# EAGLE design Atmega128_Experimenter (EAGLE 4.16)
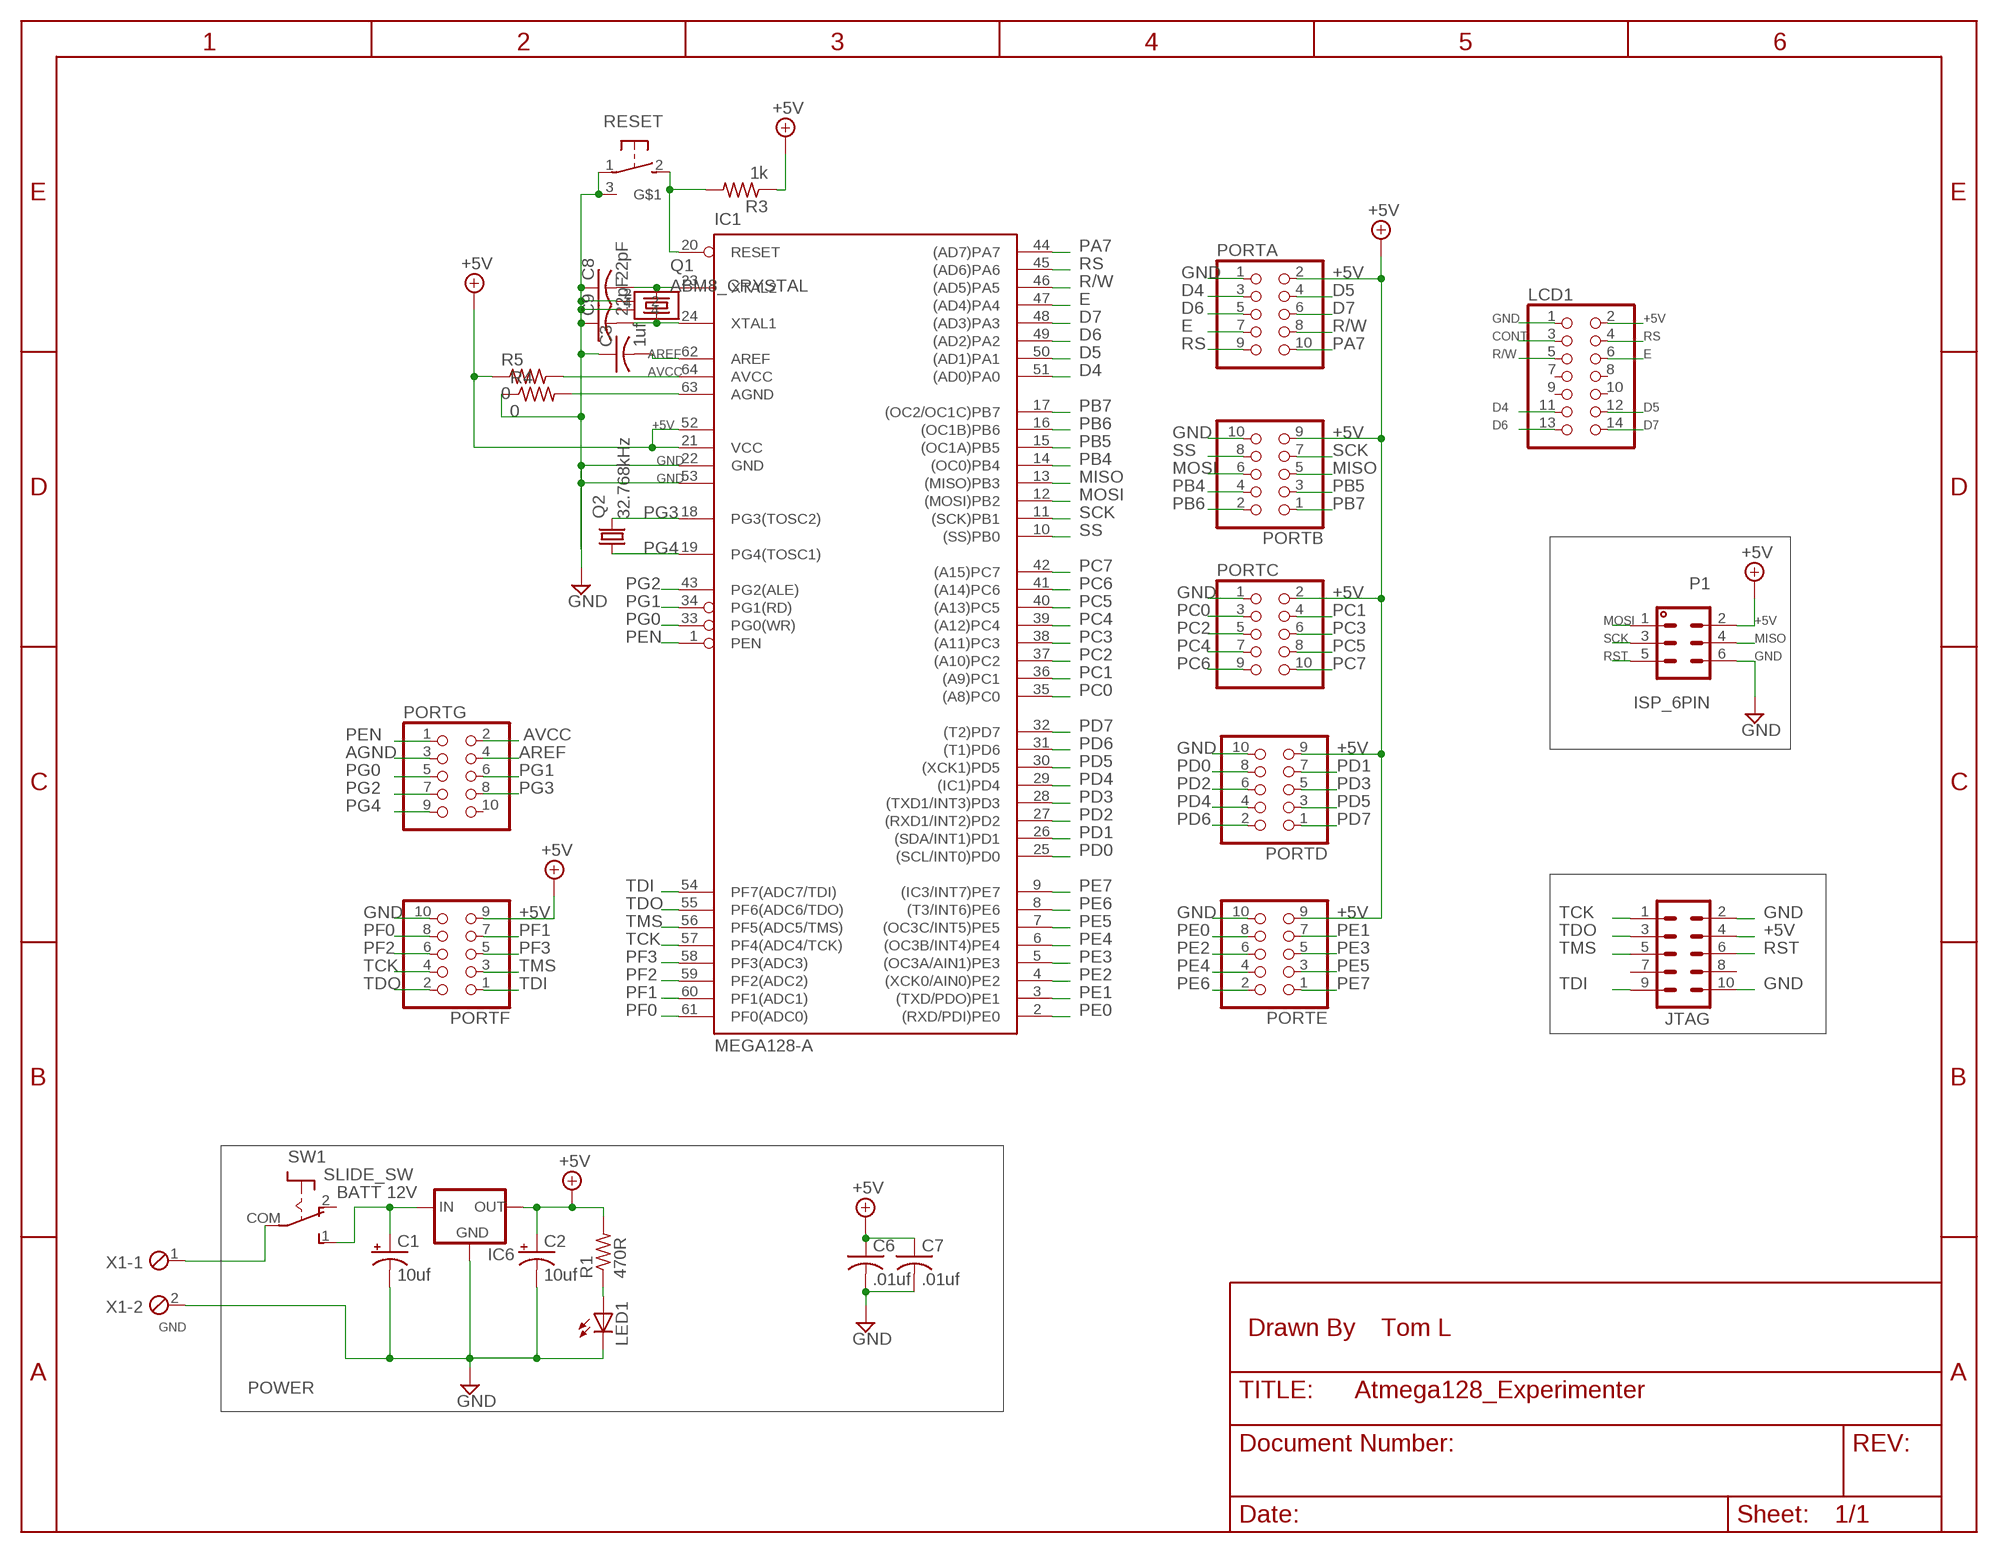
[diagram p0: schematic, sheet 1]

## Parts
C1  10uf  CPOL-US153CLV-0505  [153CLV-0505]
C2  10uf  CPOL-US153CLV-0505  [153CLV-0505]
C3  1uf  C-USC0603  [C0603]
C6  .01uf  C-USC0603  [C0603]
C7  .01uf  C-USC0603  [C0603]
C8  22pF  C-USC0603  [C0603]
C9  22pF  C-USC0603  [C0603]
IC1  MEGA128-A  [TQFP64]
IC6  78XXL  [78XXL]
JTAG  MA05-2  [MA05-2]
LCD1  PINHD-2X7  [2X07]
LED1  LEDCHIP-LED0805  [CHIP-LED0805]
P1  ISP_6PIN  [2X03]
PORTA  PINHD-2X5  [2X05]
PORTB  PINHD-2X5  [2X05]
PORTC  PINHD-2X5  [2X05]
PORTD  PINHD-2X5  [2X05]
PORTE  PINHD-2X5  [2X05]
PORTF  PINHD-2X5  [2X05]
PORTG  PINHD-2X5  [2X05]
Q1  ABM8_CRYSTAL  [ABM8]
Q2  32.768kHz  CRYTALTC26V  [TC26V]
R1  470R  R-US_R0603  [R0603]
R3  1k  R-US_R0603  [R0603]
R4  0  R-US_R0603  [R0603]
R5  0  R-US_R0603  [R0603]
RESET  B3U  [B3U]
SW1  SLIDE_SW  [EG1218]
X1  MPT2  [2POL254]

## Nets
12V_IN: SW1.COM X1.1
+5V: C2.+ C6.1 C7.1 IC1.21(VCC) IC1.52(VCC1) IC6.OUT JTAG.4 LCD1.2 P1.2(VDD) PORTA.2 PORTB.9 PORTC.2 PORTD.9 PORTE.9 PORTF.9 R1.2 R3.1 R5.1
+12V: C1.+ IC6.IN SW1.1
AGND: IC1.63(AGND) PORTG.3 R4.2
AREF: C3.2 IC1.62(AREF) PORTG.4
AVCC: IC1.64(AVCC) PORTG.2 R5.2
CONT: LCD1.3
D4: IC1.51((AD0)PA0) LCD1.11 PORTA.3
D5: IC1.50((AD1)PA1) LCD1.12 PORTA.4
D6: IC1.49((AD2)PA2) LCD1.13 PORTA.5
D7: IC1.48((AD3)PA3) LCD1.14 PORTA.6
E: IC1.47((AD4)PA4) LCD1.6 PORTA.7
GND: C1.- C2.- C3.1 C6.2 C7.2 C8.1 C9.1 IC1.22(GND) IC1.53(GND1) IC6.GND JTAG.2 JTAG.10 LCD1.1 LED1.C P1.6(GND) PORTA.1 PORTB.10 PORTC.1 PORTD.10 PORTE.10 PORTF.10 Q1.2 Q1.4 R4.1 RESET.1 RESET.3(G$1) X1.2
MISO: IC1.13((MISO)PB3) P1.4(MISO) PORTB.5
MOSI: IC1.12((MOSI)PB2) P1.1(MOSI) PORTB.6
N$5: LED1.A R1.1
PA7: IC1.44((AD7)PA7) PORTA.10
PB4: IC1.14((OC0)PB4) PORTB.4
PB5: IC1.15((OC1A)PB5) PORTB.3
PB6: IC1.16((OC1B)PB6) PORTB.2
PB7: IC1.17((OC2/OC1C)PB7) PORTB.1
PC0: IC1.35((A8)PC0) PORTC.3
PC1: IC1.36((A9)PC1) PORTC.4
PC2: IC1.37((A10)PC2) PORTC.5
PC3: IC1.38((A11)PC3) PORTC.6
PC4: IC1.39((A12)PC4) PORTC.7
PC5: IC1.40((A13)PC5) PORTC.8
PC6: IC1.41((A14)PC6) PORTC.9
PC7: IC1.42((A15)PC7) PORTC.10
PD0: IC1.25((SCL/INT0)PD0) PORTD.8
PD1: IC1.26((SDA/INT1)PD1) PORTD.7
PD2: IC1.27((RXD1/INT2)PD2) PORTD.6
PD3: IC1.28((TXD1/INT3)PD3) PORTD.5
PD4: IC1.29((IC1)PD4) PORTD.4
PD5: IC1.30((XCK1)PD5) PORTD.3
PD6: IC1.31((T1)PD6) PORTD.2
PD7: IC1.32((T2)PD7) PORTD.1
PE0: IC1.2((RXD/PDI)PE0) PORTE.8
PE1: IC1.3((TXD/PDO)PE1) PORTE.7
PE2: IC1.4((XCK0/AIN0)PE2) PORTE.6
PE3: IC1.5((OC3A/AIN1)PE3) PORTE.5
PE4: IC1.6((OC3B/INT4)PE4) PORTE.4
PE5: IC1.7((OC3C/INT5)PE5) PORTE.3
PE6: IC1.8((T3/INT6)PE6) PORTE.2
PE7: IC1.9((IC3/INT7)PE7) PORTE.1
PEN: IC1.1(PEN) PORTG.1
PF0: IC1.61(PF0(ADC0)) PORTF.8
PF1: IC1.60(PF1(ADC1)) PORTF.7
PF2: IC1.59(PF2(ADC2)) PORTF.6
PF3: IC1.58(PF3(ADC3)) PORTF.5
PG0: IC1.33(PG0(WR)) PORTG.5
PG1: IC1.34(PG1(RD)) PORTG.6
PG2: IC1.43(PG2(ALE)) PORTG.7
PG3: IC1.18(PG3(TOSC2)) PORTG.8 Q2.2
PG4: IC1.19(PG4(TOSC1)) PORTG.9 Q2.1
R/W: IC1.46((AD5)PA5) LCD1.5 PORTA.8
RS: IC1.45((AD6)PA6) LCD1.4 PORTA.9
RST: IC1.20(RESET) JTAG.6 P1.5(RST) R3.2 RESET.2
SCK: IC1.11((SCK)PB1) P1.3(SCK) PORTB.7
SS: IC1.10((SS)PB0) PORTB.8
TCK: IC1.57(PF4(ADC4/TCK)) JTAG.1 PORTF.4
TDI: IC1.54(PF7(ADC7/TDI)) JTAG.9 PORTF.1
TDO: IC1.55(PF6(ADC6/TDO)) JTAG.3 PORTF.2
TMS: IC1.56(PF5(ADC5/TMS)) JTAG.5 PORTF.3
XTAL1: C9.2 IC1.24(XTAL1) Q1.1
XTAL2: C8.2 IC1.23(XTAL2) Q1.3
Unconnected: JTAG.7 JTAG.8 LCD1.7 LCD1.8 LCD1.9 LCD1.10 PORTG.10 SW1.2

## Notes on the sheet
- BATT 12V
- Drawn By | Tom L
- POWER

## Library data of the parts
C1 C2 = rcl:CPOL-US: POLARIZED CAPACITOR, American symbol
C3 C6-C9 = rcl:C-US: CAPACITOR, American symbol
IC1 = atmel:MEGA128: MICROCONTROLLER 128 Kbytes FLASH 4 Kbytes SRAM 4 Kbytes EEPROM DUAL USART 8-channel 10 bit ADC Source: avr.lbr
IC6 = v-reg:78XXL: VOLTAGE REGULATOR
JTAG = con-lstb:MA05-2: PIN HEADER
LCD1 = pinhead:PINHD-2X7: PIN HEADER
LED1 = led:LED: LED
P1 = mylib:ISP_6PIN: AVR 6Pin ISP Connector
PORTA PORTB PORTC PORTD PORTE PORTF PORTG = pinhead:PINHD-2X5: PIN HEADER
Q1 = mylib:ABM8_CRYSTAL: Crystal SMD ABM8-16.000MHZ-B2-T
Q2 = crystal:CRYTAL: CRYSTAL
R1 R3-R5 = rcl:R-US_: RESISTOR, American symbol
RESET = mylib:B3U: Omron Ultra-Small Tactile Switch
SW1 = mylib:SLIDE_SW: EG1218 Slide Switch thru hole SPDT
X1 = con-phoenix-254:MPT2: PHOENIX CONNECTOR

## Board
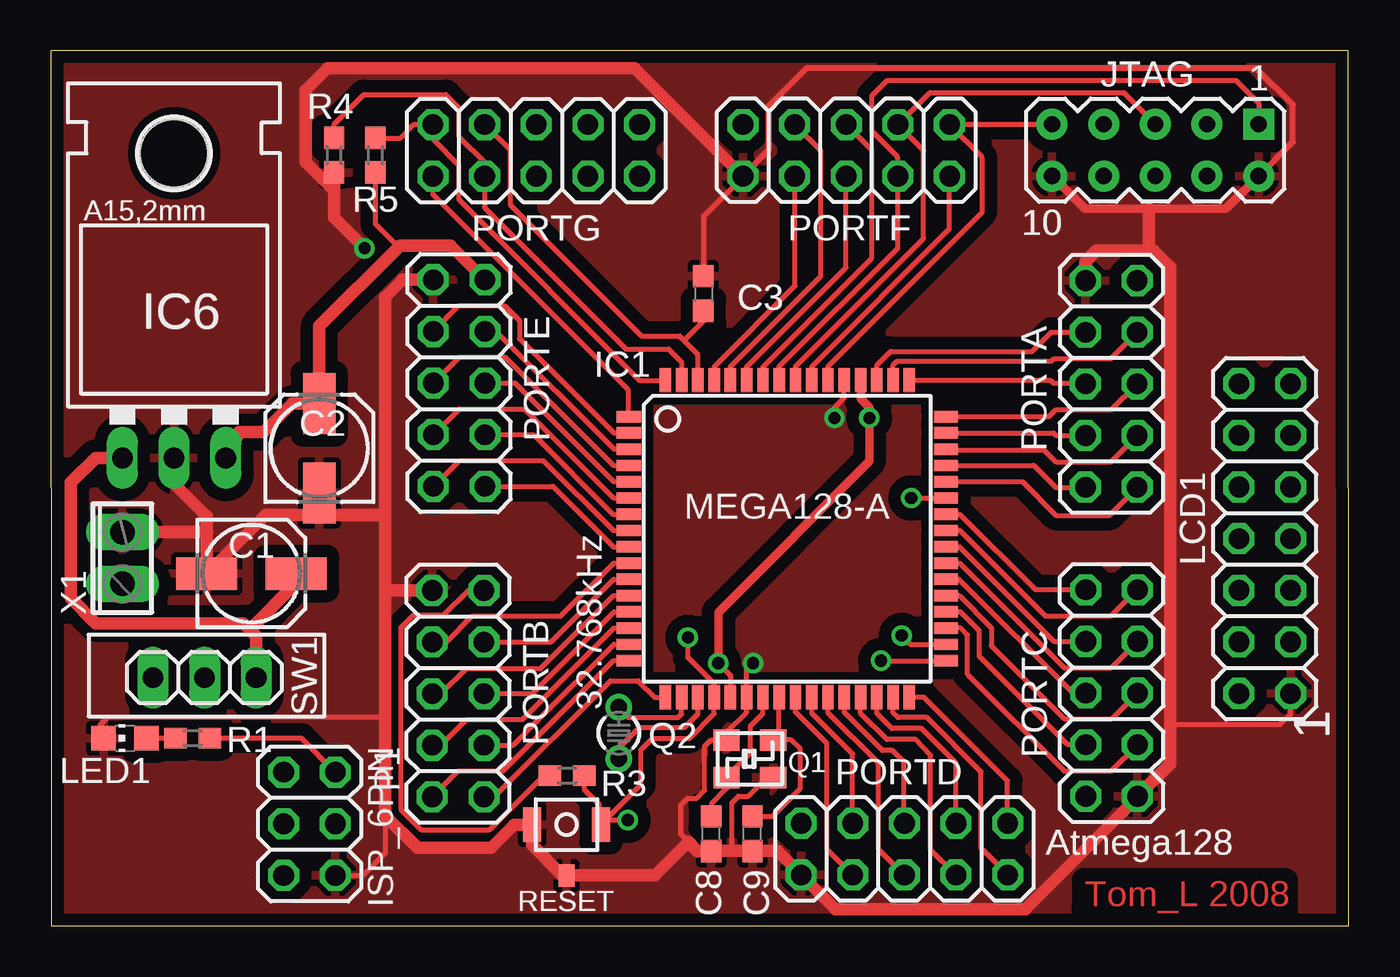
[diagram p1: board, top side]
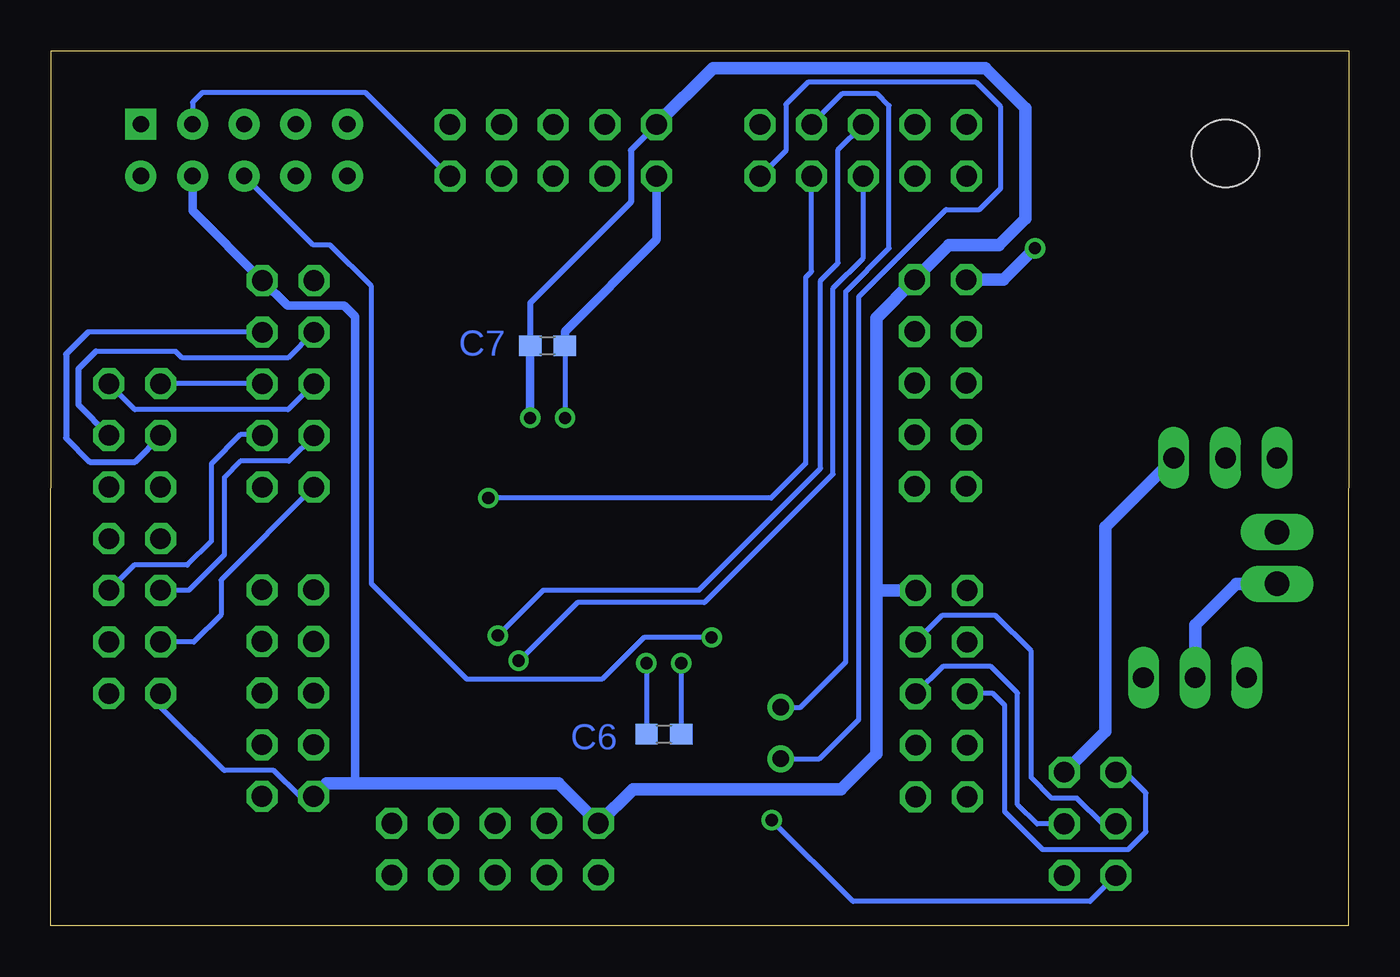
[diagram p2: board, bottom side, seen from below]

Size 63.83 x 43.04 mm. Coordinates in mm from the lower left corner, seen from the top.
Outline: 0.03,0 63.83,0 63.8,43.04 0,43.04 0.03,0
Copper layers (1*16): Top 0.035mm / dielectric 1.5mm / Bottom 0.035mm
Design rules "GOLDPHOENIX_8mils": minimum track width 10mil, minimum drill 15mil, track to track 8mil, track to pad 8mil, pad to pad 8mil, via to via 8mil, smd to smd 8mil, copper to edge 20mil, drill to drill 10mil, minimum pad ring 10mil, minimum via ring 8mil, stop-mask expansion 0mil, vias tented up to drill 0mil, thermal gap 10mil

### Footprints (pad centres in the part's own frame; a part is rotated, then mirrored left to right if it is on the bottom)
153CLV-0505 = smd 3 x 1.6: + 2.2,0; - -2.2,0
C0603 = smd 1.1 x 1: 1 -0.85,0; 2 0.85,0
TQFP64 = smd 1.194 x 0.559: 1 -7.8,6; 2 -7.8,5.2; 3 -7.8,4.4; 4 -7.8,3.6; 5 -7.8,2.8; 6 -7.8,2; 7 -7.8,1.2; 8 -7.8,0.4; 9 -7.8,-0.4; 10 -7.8,-1.2; 11 -7.8,-2; 12 -7.8,-2.8; 13 -7.8,-3.6; 14 -7.8,-4.4; 15 -7.8,-5.2; 16 -7.8,-6; 33 7.8,-6; 34 7.8,-5.2; 35 7.8,-4.4; 36 7.8,-3.6; 37 7.8,-2.8; 38 7.8,-2; 39 7.8,-1.2; 40 7.8,-0.4; 41 7.8,0.4; 42 7.8,1.2; 43 7.8,2; 44 7.8,2.8; 45 7.8,3.6; 46 7.8,4.4; 47 7.8,5.2; 48 7.8,6 | smd 0.559 x 1.194: 17 -6,-7.8; 18 -5.2,-7.8; 19 -4.4,-7.8; 20 -3.6,-7.8; 21 -2.8,-7.8; 22 -2,-7.8; 23 -1.2,-7.8; 24 -0.4,-7.8; 25 0.4,-7.8; 26 1.2,-7.8; 27 2,-7.8; 28 2.8,-7.8; 29 3.6,-7.8; 30 4.4,-7.8; 31 5.2,-7.8; 32 6,-7.8; 49 6,7.8; 50 5.2,7.8; 51 4.4,7.8; 52 3.6,7.8; 53 2.8,7.8; 54 2,7.8; 55 1.2,7.8; 56 0.4,7.8; 57 -0.4,7.8; 58 -1.2,7.8; 59 -2,7.8; 60 -2.8,7.8; 61 -3.6,7.8; 62 -4.4,7.8; 63 -5.2,7.8; 64 -6,7.8
78XXL = drill 1.016 long: GND 0,-3.81; IN -2.54,-3.81; OUT 2.54,-3.81 | hole 3.302: 0,11.176
MA05-2 = drill 0.8 pad 1.524 square: 1 -5.08,-1.27 | drill 0.8 pad 1.524 round: 2 -5.08,1.27; 3 -2.54,-1.27; 4 -2.54,1.27; 5 0,-1.27; 6 0,1.27; 7 2.54,-1.27; 8 2.54,1.27; 9 5.08,-1.27; 10 5.08,1.27
2X07 = drill 1.016 octagon: 1 -7.62,-1.27; 2 -7.62,1.27; 3 -5.08,-1.27; 4 -5.08,1.27; 5 -2.54,-1.27; 6 -2.54,1.27; 7 0,-1.27; 8 0,1.27; 9 2.54,-1.27; 10 2.54,1.27; 11 5.08,-1.27; 12 5.08,1.27; 13 7.62,-1.27; 14 7.62,1.27
CHIP-LED0805 = smd 1.2 x 1.2: A 0,-1.05; C 0,1.05
2X03 = drill 1.016 octagon: 1 -2.54,-1.27; 2 -2.54,1.27; 3 0,-1.27; 4 0,1.27; 5 2.54,-1.27; 6 2.54,1.27
2X05 = drill 1.016 octagon: 1 -5.08,-1.27; 2 -5.08,1.27; 3 -2.54,-1.27; 4 -2.54,1.27; 5 0,-1.27; 6 0,1.27; 7 2.54,-1.27; 8 2.54,1.27; 9 5.08,-1.27; 10 5.08,1.27
ABM8 = smd 1.3 x 1.05: 1 -1.15,-0.925; 2 1.15,-0.925; 3 1.15,0.925; 4 -1.15,0.925
TC26V = drill 0.813 round: 1 -1.27,0; 2 1.27,0
R0603 = smd 1.1 x 1: 1 -0.85,0; 2 0.85,0
B3U = smd 0.9 x 1.7: 1 -1.7,0; 2 1.7,0 | smd 0.8 x 1.1: 3 0,-2.5
EG1218 = drill 1.016 long: 1 -2.355,2.1; 2 2.725,2.1; COM 0.185,2.1
2POL254 = drill 1.2 long: 1 -1.27,0; 2 1.27,0

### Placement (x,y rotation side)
C1  9.87,17.33 0 top
C2  13.2,23.49 90 top
C3  32.09,31.11 270 top
C6  33.68,9.42 180 bottom
C7  39.4,28.54 0 bottom
C8  32.48,4.53 90 top
C9  34.51,4.53 90 top
IC1  36.22,19.04 0 top
IC6  6.06,26.82 0 top
JTAG  54.32,38.16 180 top
LCD1  59.7,19.04 90 top
LED1  3.65,9.23 90 top
P1  12.72,5.01 270 top
PORTA  52.15,26.66 270 top
PORTB  20.03,11.42 90 top
PORTC  52.18,11.45 90 top
PORTD  41.98,3.78 180 top
PORTE  20.08,26.7 90 top
PORTF  39.12,38.14 180 top
PORTG  23.87,38.14 0 top
Q1  34.38,8.22 180 top
Q2  27.94,9.49 90 top
R1  6.98,9.23 0 top
R3  25.4,7.39 0 top
R4  13.93,37.9 90 top
R5  15.97,37.9 90 top
RESET  25.36,4.98 0 top
SW1  7.74,14.31 180 top
X1  3.52,18.09 90 top

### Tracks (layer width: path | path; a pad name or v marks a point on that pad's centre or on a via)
12V_IN
  Bottom 0.61: X1.1 5.52,16.82 7.55,14.79 SW1.COM
+5V  (via drill 0.6)
  Top 0.254: 39.84,26.85 IC1.52 | IC1.21 33.43,12.31 v32.82,12.92 | R3.1 24.25,7.39 21.58,4.72 18.22,4.72 17.2,5.74 17.2,14.66 17.81,15.27 19.3,15.27 20.54,16.5 PORTB.9 | P1.2 | P1.2 | R1.2 12.31,9.23 P1.2 | 17.11,33.36 17.09,33.38 15.96,34.51 R5.1 | 40.25,25.49
  Top 0.406: 39.84,26.85 39.84,25.9 40.25,25.49 v40.25,24.98 40.25,22.85 32.82,15.42 v32.82,12.92
  Top 0.61: 21.36,31.78 PORTE.9 21.33,31.78 19.65,33.46 17.17,33.46 17.09,33.38 13.2,29.49 C2.+ | C2.+ 11.88,25.69 10.47,24.28 9.27,24.28 9.23,24.25 IC6.OUT | C2.+ 13.2,25.68
  Bottom 0.254: v40.25,24.98 v40.25,24.99 | C6.1 v32.83,12.92 v32.82,12.92 | 50.89,6.34 PORTC.2 51.57,6.36 52.86,7.65 55.3,7.65 58.41,10.76 58.41,11.36 58.43,11.38 LCD1.2
  Bottom 0.305: PORTF.9 35.3,38.15 35.3,35.59 40.25,30.63 C7.1 | C7.1 | C7.1 | PORTC.2 50.92,6.38 50.92,6.41
  Bottom 0.406: 48.86,7.01 48.86,29.97 49.4,30.51 52.19,30.51 PORTA.2 56.86,35.18 JTAG.4 | C7.1 v40.25,24.98
  Bottom 0.61: 23.24,16.5 23.24,8.47 24.98,6.72 35.21,6.72 PORTD.9 38.87,7.01 48.86,7.01 50.25,7.01 PORTC.2 | 23.24,16.5 23.23,16.5 | PORTB.9 23.24,16.5 | 23.24,16.5 23.24,29.9 21.36,31.78 | 21.36,31.78 PORTE.9 | 21.36,31.78 19.65,33.49 17.2,33.49 15.9,34.79 15.9,40.22 17.87,42.19 31.27,42.19 PORTF.9 | P1.2 11.96,9.58 11.96,19.61 8.6,22.98 IC6.OUT | PORTC.2 50.92,6.34 | PORTC.2
+12V
  Top 0.61: SW1.1 10.1,12.19 10.09,12.19 10.09,14.25 9.77,14.57 | IC6.IN 2.22,23.01 0.98,21.81 0.98,16.12 2.22,14.88 9.46,14.88 9.77,14.57 | C1.+ 12.07,16.86 9.77,14.57
AGND
  Top 0.254: 31.01,26.85 IC1.63 31.01,26.85 | 31.01,26.85 31.01,27.74 30.38,28.38 28.28,28.38 21.33,35.33 PORTG.3 21.33,37.55 20.06,38.82 20.06,40.25 19.43,40.89 15.39,40.89 13.93,39.43 R4.2
AREF
  Top 0.254: 31.84,26.85 IC1.62 | 31.84,26.73 31.82,26.75 IC1.62 | PORTG.4 22.6,38.14 22.6,35.46 29.05,29.01 30.92,29.01 31.14,28.79 | IC1.62 31.81,26.86 31.81,28.12 31.14,28.79 | 31.14,28.79 | C3.2 32.09,29.74 31.14,28.79
AVCC
  Top 0.254: 30.19,26.85 30.2,26.84 IC1.64 30.22,26.82 28.95,26.82 20.06,35.74 20.06,37.43 18.79,38.7 18.79,39.36 | 18.79,39.36 | 18.79,39.36 PORTG.2 18.77,39.41 18.76,39.43 17.87,39.43 17.2,38.75 R5.2
D4
  Top 0.254: IC1.51 40.62,27.57 41.3,28.25 48.25,28.25 49.21,29.2 50.86,29.2 PORTA.3
  Bottom 0.254: PORTA.3 50.91,29.17 | 50.92,29.17 52.16,27.93 57.37,27.93 57.68,28.25 61.62,28.25 | 50.92,29.17
  Bottom 0.305: LCD1.11 62.48,25.63 62.48,27.39 61.62,28.25 | 50.91,29.17 50.92,29.17
D5
  Top 0.254: IC1.50 41.42,27.58 41.62,27.77 49.21,27.77 49.33,27.9 52.13,27.9 PORTA.4 | PORTA.4 | PORTA.4
  Bottom 0.254: PORTA.4 62,29.2
  Bottom 0.305: 62,29.2 63.08,28.12 63.08,24 61.91,22.82 59.68,22.82 58.41,24.09 58.43,24.11 LCD1.12
D6
  Top 0.254: IC1.49 49.15,26.84 49.3,26.7 50.86,26.7 PORTA.5
  Bottom 0.254: 50.92,26.63 50.91,26.63 PORTA.5 | 50.92,26.63 52.16,25.39 59.7,25.39 LCD1.13 | 50.92,26.63
D7
  Top 0.254: PORTA.6 | PORTA.6 | 49.43,25.39 52.16,25.39 PORTA.6 | 49.43,25.39 | IC1.48 49.08,25.04 49.43,25.39
  Bottom 0.254: PORTA.6 LCD1.14 | LCD1.14
E
  Top 0.254: PORTA.7 49.43,24.12 | 49.43,24.12 | IC1.47 49.31,24.24 49.43,24.12
  Bottom 0.254: LCD1.6 57.05,16.5 55.3,18.25 55.3,22.06 54.51,22.85 52.13,22.85 50.86,24.12 | 50.86,24.12 | PORTA.7 50.86,24.12
GND  (via drill 0.6)
  Top 0.254: 53.46,6.38 PORTC.1 53.43,6.34 | C9.1 34.48,3.68 34.47,3.68 | 33.49,3.68 | 31.36,4.12 30.98,4.5 30.98,5.96 31.3,6.28 31.78,6.28 32.16,6.66 32.16,8.82 32.48,9.14 Q1.2 | C8.1 | 25.17,2.47 25.18,2.48 RESET.3 | v38.54,24.98 38.54,25.49 39.02,25.96 39.02,26.85 IC1.53 | LED1.C 2.41,9.87 2.82,10.28 16.44,10.28 | 36.92,2.5 PORTD.10 | IC1.22 | IC1.22 | v34.54,12.92 34.22,12.6 IC1.22 | JTAG.10 49.24,36.86 | 16.44,5.8 | 16.44,5.8 16.44,3.58 15.33,2.47 P1.6 | Q1.2 33.45,9.14 | Q1.4 35.23,7.29 34.32,6.38 33.81,6.38 33.49,6.06 33.49,3.68 | 33.49,3.68 | LCD1.1 60.97,10.42 60.45,9.9 55.05,9.9 55.02,9.9 | PORTF.10 34.06,36.86 32.09,34.89 C3.1 | IC1.22 34.22,10.5 33.17,9.49 33.24,9.42 Q1.2 | Q1.2 | Q1.2 | 50.21,35.92
  Top 0.305: JTAG.2 61.08,38.57 61.08,40.38 59.27,42.19 37.17,42.19 35.3,40.32 35.3,38.16 34.03,36.89 PORTF.10 | 55.05,32.28 54.99,32.28 | 55.05,8.44
  Top 0.406: JTAG.2 57.78,35.27 54,35.27 50.86,35.27 50.21,35.92 JTAG.10
  Top 0.61: PORTA.1 50.88,32.66 51.43,33.2 54,33.2 | PORTC.1 55.05,7.96 55.05,8.44 55.05,9.9 55.05,32.28 55.05,32.41 54.26,33.2 54,33.2 | C8.1 33.49,3.68 34.47,3.68 | C8.1 31.81,3.68 31.36,4.12 29.72,2.48 RESET.3 | 25.17,2.47 23.66,3.98 RESET.1 22.79,4.98 21.65,3.84 18.03,3.84 16.47,5.39 16.44,6.03 | PORTE.10 17.3,31.78 16.44,30.92 16.44,29.62 | 16.44,6.03 16.44,10.28 16.44,16.5 | 16.44,6.03 16.44,5.8 | 16.44,16.5 16.44,20.22 | 16.44,20.22 16.44,29.62 | PORTB.10 16.44,16.5 | PORTD.10 38.59,0.82 47.94,0.82 53.46,6.34 PORTC.1 | 53.46,6.35 PORTC.1 | 16.44,29.62 16.43,29.63 | C9.1 35.74,3.68 36.92,2.5 | 54,33.2 | 54,33.2 | 54,33.2 54,35.27 | 7.67,19.36 C1.- 7.68,17.33 10.57,20.22 13.04,20.22 | 7.67,19.36 7.67,20.16 7.64,20.16 6.06,21.74 6.06,22.98 IC6.GND | 16.44,20.22 13.04,20.22 | 13.04,20.22 13.04,20.31 13.2,20.47 C2.- | 13.93,36.16 13.93,34.82 v15.43,33.33 | 13.93,36.16 R4.1 | 7.67,19.36 7.68,19.36 | 7.67,19.36 X1.2 | 13.93,36.16 12.54,37.55 12.54,41.11 13.62,42.19 28.7,42.19 34.03,36.86
  Bottom 0.254: C7.2 v38.55,24.99 v38.54,24.98 | C6.2 v34.53,12.91 v34.54,12.92 | PORTE.10
  Bottom 0.406: C7.2 38.55,28.51 38.54,28.51 38.54,29.24 34.03,33.74 34.03,36.86 34.04,36.86 PORTF.10
  Bottom 0.61: v15.43,33.33 16.98,31.78 PORTE.10
  pour Top (isolate 0.61): 0.25,42.82 63.62,42.82 63.62,0.22 0.25,0.22
MISO
  Top 0.254: IC1.13 27.7,15.44 24.95,12.69 | 24.95,12.69 | 24.95,12.69 23.68,11.42 PORTB.5
  Bottom 0.254: PORTB.5 19.97,12.76 17.58,12.76 16.28,11.46 16.28,5.96 15.33,5.01 | P1.4 15.33,5.01 | 15.33,5.01 | 15.33,5.01
MOSI
  Top 0.254: 27.67,16.24 IC1.12 | PORTB.6 | PORTB.6 19.2,11.42 20.44,12.66 24.09,12.66 27.67,16.24 | PORTB.6 | 27.67,16.24 27.68,16.25
  Bottom 0.254: P1.1 10.98,7.55 9.96,6.53 9.96,4.63 10.85,3.74 15.04,3.74 16.92,5.61 16.92,10.85 17.49,11.42 18.73,11.42 PORTB.6
N$5
  Top 0.254: LED1.A 4.73,9.23 | 4.73,9.23 R1.1 | 4.73,9.23
PA7
  Top 0.254: PORTA.10 53.42,21.56 53.43,21.55 52.06,20.19 49.43,20.19 47.77,21.84 IC1.44
PB4
  Top 0.254: IC1.14 27.69,14.64 23.2,10.15 20.44,10.15 19.17,8.88 PORTB.4
PB5
  Top 0.254: IC1.15 27.69,13.84 24,10.15 | 24,10.15 | PORTB.3 22.72,8.88 24,10.15
PB6
  Top 0.254: IC1.16 27.68,13.04 22.25,7.61 20.03,7.61 PORTB.2
PB7
  Top 0.254: IC1.17 29.71,11.23 28.89,12.06 27.52,12.06 21.8,6.34 PORTB.1
PC0
  Top 0.254: PORTC.3 53.46,8.92 | PORTC.3 | PORTC.3 52.16,7.61 49.84,7.61 45.08,12.38 45.08,14.31 44.75,14.64 IC1.35
PC1
  Top 0.254: 50.89,8.88 PORTC.4 50.89,8.92 50,8.92 45.65,13.26 45.65,14.53 44.74,15.44 IC1.36
PC2
  Top 0.254: PORTC.5 53.46,11.46 | PORTC.5 | PORTC.5 52.19,10.19 49.84,10.19 46.25,13.77 46.25,14.66 44.67,16.24 | IC1.37 44.67,16.24 | 44.67,16.24 44.67,16.25 | 44.67,16.24
PC3
  Top 0.254: IC1.38 | IC1.38 44.67,17.04 50.26,11.46 50.92,11.46 | 50.92,11.46 | 50.92,11.46 PORTC.6
PC4
  Top 0.254: PORTC.7 53.46,14 | PORTC.7 | PORTC.7 52.16,12.69 49.84,12.69 44.69,17.84 IC1.39
PC5
  Top 0.254: IC1.40 44.69,18.64 49.33,14 50.92,14 | 50.92,14 | 50.92,14 PORTC.8
PC6
  Top 0.254: PORTC.9 53.43,16.54 52.13,15.23 48.92,15.23 44.7,19.46 44.69,19.44 IC1.41
PC7
  Top 0.254: IC1.42 44.71,20.24 48.41,16.54 50.92,16.54 | 50.92,16.54 | 50.92,16.54 PORTC.10
PD0
  Top 0.254: IC1.25 36.62,10.52 38.16,8.98 38.16,3.77 PORTD.8
PD1
  Top 0.254: IC1.26 37.42,10.45 39.43,8.47 PORTD.7
PD2
  Top 0.254: IC1.27 38.22,10.47 40.7,8.03 40.7,7.39 40.7,3.77 PORTD.6
PD3
  Top 0.254: IC1.28 39.02,10.5 40.89,8.63 41.4,8.63 41.97,8.06 41.97,5.01 41.98,5.02 PORTD.5
PD4
  Top 0.254: IC1.29 39.82,10.46 41.11,9.17 42.54,9.17 43.27,8.41 43.27,3.74 PORTD.4
PD5
  Top 0.254: IC1.30 40.62,10.45 41.37,9.71 42.83,9.71 44.51,8.03 PORTD.3
PD6
  Top 0.254: IC1.31 41.42,10.48 41.65,10.25 43.08,10.25 45.75,7.58 45.75,3.84 47.08,2.5 | 47.08,2.5 | PORTD.2 47.08,2.5
PD7
  Top 0.254: PORTD.1 47.06,5.09 47.05,5.11 47.05,7.14 42.94,11.24 IC1.32
PE0
  Top 0.254: IC1.2 27.69,24.24 23.05,28.89 23.05,29.78 22.32,30.51 20.06,30.51 18.79,29.24 | 18.79,29.24 | PORTE.8 18.79,29.24
PE1
  Top 0.254: 27.69,23.44 IC1.3 | 27.69,23.44 | PORTE.7 21.9,29.24 27.69,23.44
PE2
  Top 0.254: PORTE.6 18.82,26.7 20.09,27.97 22.35,27.97 27.67,22.64 IC1.4
PE3
  Top 0.254: 27.67,21.84 IC1.5 | 27.67,21.84 27.68,21.84 | PORTE.5 22.82,26.7 27.67,21.84
PE4
  Top 0.254: IC1.6 27.68,21.04 23.3,25.43 20.09,25.43 18.82,24.16 PORTE.4
PE5
  Top 0.254: IC1.7 27.66,20.24 23.74,24.16 PORTE.3
PE6
  Top 0.254: PORTE.2 18.82,21.62 20.09,22.89 24.22,22.89 27.66,19.44 IC1.8
PE7
  Top 0.254: IC1.9 27.67,18.64 24.69,21.62 PORTE.1
PEN
  Top 0.254: PORTG.1 18.79,35.97 28.41,26.35 28.41,25.01 28.42,25.02 IC1.1
PF0
  Top 0.254: IC1.61 32.63,27.52 36.6,31.49 36.6,36.86 PORTF.8
PF1
  Top 0.254: 37.87,38.12 PORTF.7 | IC1.60 33.42,27.51 37.87,31.97 37.87,38.12 | 37.87,38.12 37.87,38.13
PF2
  Top 0.254: IC1.59 34.22,27.49 39.11,32.38 39.11,36.86 39.12,36.86 PORTF.6
PF3
  Top 0.254: 40.38,38.15 PORTF.5 | IC1.58 35.02,27.5 40.38,32.85 40.38,38.15 | 40.38,38.15 40.38,38.16
PG0  (via drill 0.6)
  Top 0.254: IC1.33 v40.83,13.04
  Bottom 0.254: PORTG.5 23.87,32.85 25.36,31.36 25.36,22.22 31.68,15.9 37.94,15.9 40.79,13.04 v40.83,13.04
PG1  (via drill 0.6)
  Top 0.254: IC1.34 44.01,13.84 42.29,13.84 v41.84,14.28
  Bottom 0.254: PORTG.6 25.11,38.17 25.11,32.6 25.97,31.74 25.97,22.5 31.97,16.5 39.62,16.5 v41.84,14.28
PG2  (via drill 0.6)
  Top 0.254: 44,21.04 | 44,21.04 IC1.43 | v42.32,21.04 44,21.04
  Bottom 0.254: PORTG.7 26.41,32.19 26.7,31.9 26.7,22.76 28.41,21.04 v42.32,21.04
PG3
  Top 0.254: IC1.18 31.02,10.41 30.86,10.25 28.41,10.25 27.93,10.73 27.94,10.73 Q2.2
  Bottom 0.254: PORTG.8 26.41,39.43 24.92,40.92 23.17,40.92 22.6,40.35 22.6,33.33 24.73,31.2 24.73,12.98 26.95,10.76 Q2.2
PG4
  Top 0.254: IC1.19 31.82,10.42 31.17,9.77 28.95,9.77 27.93,8.76 27.93,8.25 27.94,8.25 Q2.1
  Bottom 0.254: PORTG.9 28.94,36.87 27.68,38.13 27.68,40.41 26.6,41.49 18.31,41.49 17.11,40.28 17.11,36.28 18.16,35.24 19.81,35.24 24.09,30.95 24.09,10.15 26.03,8.22 Q2.1
R/W
  Top 0.254: IC1.46 44.02,23.41 48.84,23.41 49.43,22.82 52.13,22.82 PORTA.8 | PORTA.8 | PORTA.8
  Bottom 0.254: LCD1.5 59.73,17.74 57.11,17.74 55.94,18.92 55.94,22.73 54.51,24.16 53.43,24.16 PORTA.8
RS
  Top 0.254: PORTA.9 50.86,21.55 49.43,21.55 48.34,22.64 IC1.45
  Bottom 0.254: LCD1.4 56.8,13.96 55.46,15.3 55.46,17.01 50.92,21.55 | 50.92,21.55 50.91,21.55 PORTA.9 | 50.92,21.55
RST  (via drill 0.6)
  Top 0.254: RESET.2 | RESET.2 27.08,4.99 27.08,5.01 29.01,6.95 29.01,8.66 29.59,9.23 31.43,9.23 32.62,10.43 IC1.20 32.63,11.9 31.33,13.2 v31.33,14.19 | R3.2 26.24,6.7 26.98,5.96 26.98,5.01 27.01,4.98 RESET.2 | 27.05,4.98 | 27.05,4.98 RESET.2 | v28.38,5.2 27.27,5.2 27.05,4.98
  Bottom 0.254: v31.33,14.19 34.67,14.19 36.73,12.12 43.37,12.12 48.06,16.82 48.06,31.46 50.1,33.49 50.92,33.49 JTAG.6 | P1.5 12.73,1.2 24.38,1.2 v28.38,5.2 | v28.38,5.2
SCK
  Top 0.254: IC1.11 27.68,17.04 25.87,15.23 | 25.87,15.23 | PORTB.7 24.6,13.96 25.87,15.23
  Bottom 0.254: PORTB.7 20,15.27 17.36,15.27 15.62,13.52 15.62,7.3 14.6,6.28 13.36,6.28 12.09,5.01 P1.3
SS
  Top 0.254: IC1.10 27.69,17.84 25.08,15.23 20.73,15.23 19.46,13.96 18.73,13.96 PORTB.8
TCK
  Top 0.254: IC1.57 35.82,27.5 41.65,33.33 41.65,36.86 | 41.65,36.86 41.66,36.86 PORTF.4 41.65,36.86 | 41.65,36.86 41.65,37.81 40.38,39.08 40.38,40.82 41.14,41.59 58.29,41.59 59.4,40.47 JTAG.1
TDI
  Top 0.254: IC1.54 38.22,27.52 45.81,35.11 45.81,37.8 | 45.81,37.8 PORTF.1 44.21,39.43 JTAG.9 | 45.81,37.8 45.81,37.81
TDO
  Top 0.254: IC1.55 37.42,27.51 44.19,34.28 44.19,36.86 | 44.19,36.86 44.2,36.86 PORTF.2 44.19,36.86
  Bottom 0.254: JTAG.3 56.86,40.51 56.38,40.98 48.35,40.98 44.22,36.86 44.19,36.86 PORTF.2
TMS
  Top 0.254: 42.92,38.15 PORTF.3 41.67,39.43 41.68,39.43 43.24,40.98 52.76,40.98 JTAG.5 | IC1.56 36.62,27.51 42.92,33.81 42.92,38.15 | 42.92,38.15 42.92,38.16
XTAL1
  Top 0.254: C9.2 35.49,5.39 36.86,6.76 36.86,8.69 36.41,9.14 Q1.1 | 35.55,9.14 | 35.55,9.14 Q1.1 | IC1.24 35.82,9.51 35.55,9.14 | Q1.1 | Q1.1
XTAL2
  Top 0.254: C8.2 32.5,5.38 32.51,5.39 32.51,6.03 33.24,6.76 Q1.3 33.23,7.32 34.41,8.5 34.41,9.84 35.02,10.45 IC1.23

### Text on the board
Top: Tom_L 2008
tPlace: Atmega128
tNames: 1
_tsilk: JTAG | 1 | R4 | A15,2mm | R5 | PORTF | 10 | PORTG | C3 | PORTA | IC6 | IC1 | C2 | PORTE | MEGA128-A | C1 | LCD1 | SW1 | 32.768kHz | R1 | ISP_6PIN | PORTB | Q2 | Q1 | 1 | LED1 | PORTD | PORTC | R3 | Atmega128 | RESET | C8 | C9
